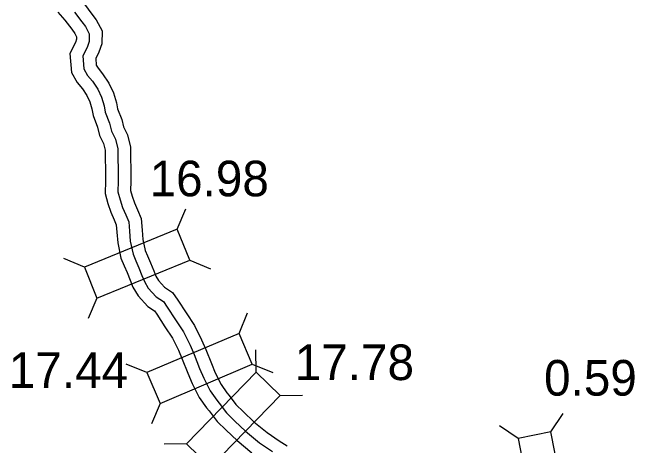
# Model space of a CAD drawing. Extents: x -83719 to 153526, y -11835 to 11446.
# Drawn here: x -4581.4 to -4335.6, y -3164.4 to -2993.1 of the extents above; entities that cross this region are included whole.
import ezdxf

# ---------------------------------------------------------------- set-up
doc = ezdxf.new("R2010")
doc.units = 0
for name, color, linetype in [('Level 15', 7, 'Continuous'), ('Level 20', 7, 'Continuous'), ('Level 58', 7, 'Continuous'), ('Level 59', 7, 'Continuous')]:
    doc.layers.add(name, color=color, linetype=linetype)

msp = doc.modelspace()

# ---------------------------------------------------------------- linework, layer by layer
at = {"layer": 'Level 15'}
for points in [[(-4552.95, -2989.91), (-4549.98, -2993.79), (-4548.3, -2996.05), (-4545.98, -3000.38), (-4546.1, -3005.55), (-4547.24, -3008.86), (-4548.45, -3011.31), (-4548.24, -3013.91), (-4547.54, -3015.18), (-4545.74, -3017.34), (-4543.25, -3021.03), (-4541.43, -3024.89), (-4540.25, -3028.88), (-4539.83, -3031.18), (-4538.2, -3035.45), (-4537.49, -3038.37), (-4535.96, -3041.46), (-4534.79, -3046.38), (-4534.76, -3050.04), (-4534.55, -3055.55), (-4534.64, -3059.9), (-4534.71, -3063.48), (-4534.08, -3065.75), (-4533.2, -3068.42), (-4531.99, -3071.15), (-4530.52, -3074.65), (-4530.1, -3079.17), (-4529.84, -3082.86), (-4528.95, -3087.19), (-4527.99, -3089.35), (-4526.84, -3092.18), (-4525.57, -3095.31), (-4524.76, -3097.34), (-4523.68, -3099.16), (-4521.35, -3101.71), (-4518.13, -3103.82), (-4516.07, -3106.85), (-4512.8, -3111.84), (-4509.43, -3116.84), (-4506.65, -3122.53), (-4505.01, -3126.41), (-4502.8, -3131.94), (-4501.24, -3135.63), (-4498.98, -3140.17), (-4496.66, -3143.45), (-4495.8, -3144.56), (-4493.06, -3148.13), (-4490.06, -3151.05), (-4485.95, -3154.91), (-4480.8, -3159.23), (-4476, -3162.5), (-4472.79, -3164.4)], [(-4563.37, -2993.08), (-4560.73, -2996.19), (-4557.96, -2999.8), (-4556.77, -3001.42), (-4556.04, -3002.78), (-4556.06, -3003.75), (-4556.5, -3005.01), (-4558.63, -3009.37), (-4558.04, -3016.84), (-4555.84, -3020.85), (-4553.75, -3023.35), (-4551.97, -3025.98), (-4550.8, -3028.47), (-4549.99, -3031.2), (-4549.51, -3033.88), (-4547.77, -3038.42), (-4546.95, -3041.81), (-4545.43, -3044.88), (-4544.78, -3047.6), (-4544.76, -3050.28), (-4544.56, -3055.64), (-4544.64, -3059.71), (-4544.73, -3064.75), (-4543.65, -3068.65), (-4542.54, -3072.02), (-4541.17, -3075.11), (-4540.33, -3077.1), (-4540.07, -3079.98), (-4539.77, -3084.23), (-4538.53, -3090.27), (-4537.19, -3093.27), (-4536.1, -3095.94), (-4534.85, -3099.03), (-4533.76, -3101.77), (-4531.74, -3105.17), (-4527.88, -3109.38), (-4525.29, -3111.08), (-4524.39, -3112.4), (-4521.13, -3117.37), (-4518.12, -3121.85), (-4515.76, -3126.68), (-4514.26, -3130.22), (-4512.05, -3135.75), (-4510.33, -3139.81), (-4507.59, -3145.31), (-4504.69, -3149.41), (-4503.71, -3150.67), (-4500.56, -3154.79), (-4496.97, -3158.28), (-4492.59, -3162.4), (-4486.84, -3167.21)]]:
    msp.add_lwpolyline(points, dxfattribs=at)
at = {"layer": 'Level 20'}
for p, q in [((-4516.29, -3078.85), (-4512.87, -3070.74)), ((-4552.96, -3093.8), (-4561.07, -3090.39)), ((-4511.31, -3091.07), (-4503.19, -3094.49)), ((-4547.98, -3106.02), (-4551.39, -3114.13)), ((-4491.76, -3120.06), (-4488.46, -3111.9)), ((-4485.04, -3135.29), (-4485.16, -3126.49)), ((-4528.22, -3135.52), (-4536.38, -3132.22)), ((-4486.61, -3132.21), (-4478.45, -3135.51)), ((-4475.57, -3144.5), (-4466.78, -3144.38)), ((-4523.07, -3147.67), (-4526.37, -3155.83)), ((-4368.69, -3158.97), (-4363.77, -3151.68)), ((-4381.64, -3161.5), (-4388.94, -3156.58)), ((-4512.65, -3163.68), (-4521.45, -3163.8))]:
    msp.add_line(p, q, dxfattribs=at)
for points in [[(-4547.98, -3106.02), (-4511.31, -3091.07), (-4516.29, -3078.85), (-4552.96, -3093.8)], [(-4523.07, -3147.67), (-4486.61, -3132.21), (-4491.76, -3120.06), (-4528.22, -3135.52)], [(-4485.04, -3135.29), (-4512.65, -3163.68), (-4503.19, -3172.88), (-4475.57, -3144.5)], [(-4361.11, -3197.84), (-4368.69, -3158.97), (-4381.64, -3161.5), (-4374.07, -3200.37)]]:
    msp.add_lwpolyline(points, close=True, dxfattribs=at)
at = {"layer": 'Level 59'}
msp.add_lwpolyline([(-4556.84, -2993.05), (-4553.97, -2996.8), (-4552.53, -2998.74), (-4551.01, -3001.58), (-4551.08, -3004.65), (-4551.87, -3006.94), (-4553.54, -3010.34), (-4553.14, -3015.37), (-4551.69, -3018.01), (-4549.74, -3020.35), (-4547.61, -3023.51), (-4546.12, -3026.68), (-4545.12, -3030.04), (-4544.67, -3032.53), (-4542.98, -3036.94), (-4542.22, -3040.09), (-4540.7, -3043.17), (-4539.79, -3046.99), (-4539.76, -3050.16), (-4539.55, -3055.6), (-4539.64, -3059.8), (-4539.72, -3064.11), (-4538.86, -3067.2), (-4537.87, -3070.22), (-4536.58, -3073.13), (-4535.43, -3075.88), (-4535.09, -3079.58), (-4534.81, -3083.54), (-4533.74, -3088.73), (-4532.59, -3091.31), (-4531.47, -3094.06), (-4530.21, -3097.17), (-4529.26, -3099.56), (-4527.71, -3102.16), (-4524.61, -3105.54), (-4521.71, -3107.45), (-4520.23, -3109.63), (-4516.97, -3114.6), (-4513.77, -3119.35), (-4511.21, -3124.61), (-4509.63, -3128.31), (-4507.42, -3133.84), (-4505.78, -3137.72), (-4503.28, -3142.74), (-4500.68, -3146.43), (-4499.76, -3147.61), (-4496.81, -3151.46), (-4493.52, -3154.67), (-4489.27, -3158.66), (-4483.82, -3163.22), (-4478.68, -3166.73)], dxfattribs=at)

# ---------------------------------------------------------------- texts
at = {"layer": 'Level 58'}
for s, p in [('16.98', (-4527.19, -3065.82)), ('17.78', (-4469.85, -3138.47)), ('17.44', (-4582.79, -3141.54)), ('0.59', (-4371.38, -3144.61))]:
    msp.add_text(s, height=14.08, dxfattribs=at).set_placement(p)

doc.saveas('drawing.dxf')
